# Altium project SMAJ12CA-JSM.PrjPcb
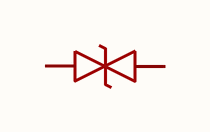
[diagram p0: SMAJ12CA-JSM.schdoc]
1 sheet, 1 parts. Net scope: global (net labels, ports and power ports of the same name join across sheets).

## Sheet SMAJ12CA-JSM.schdoc
size 127 x 101 mm

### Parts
D?  smaj12ca-jsm  [SMA_L4.3-W2.6-LS5.1-BI]  (value not drawn)

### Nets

Not connected (* = marked no-connect by the designer): D? 1 2

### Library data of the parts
D? = smaj12ca-jsm: 极性:双向;反向截止电压(Vrwm):12V;钳位电压:19.9V;峰值脉冲电流(Ipp):20.1A@10/1000us;峰值脉冲功率(Ppp):400W;击穿电压(VBR):14.7V;; Manufacturer: JSMSEMI(杰盛微); AddInBom: yes; ModelId: 75ed1d7dc9f84b5da1659e0c98b4b6e5; ModelTransform: 200.787,102.362,0,0,0,0,0,0,0; Polarity: 双向; Reverse Stand-Off Voltage (Vrwm): 12V; Clamping Voltage: 19.9V; Peak Pulse Power Dissipation (Ppp): 400W; Voltage - Breakdown: 14.7V; Reverse Leakage Current (Ir): 1uA; Number of Channels: 单路; Type: TVS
